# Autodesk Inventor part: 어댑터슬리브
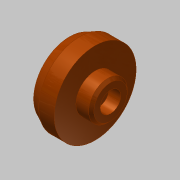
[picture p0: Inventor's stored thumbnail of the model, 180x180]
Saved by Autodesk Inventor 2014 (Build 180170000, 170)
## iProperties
Created: 2016-06
Part Number: 어댑터슬리브
Material: 강철, 탄소
Document SubType Name: Modeling
Designer: mduedu
Density: 7.87 g/cm^3
Appearance: Smooth - Light Orange
Author: mduedu
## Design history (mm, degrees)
sketch "스케치2"
  geometry: L1 (0, 0)-(0, 14); L2 (0, 14)-(-4, 16); L3 (-4, 16)-(-10, 16); L4 (-10, 16)-(-10, 7.5); L5 (-10, 7.5)-(-16, 7.5); L6 (-16, 7.5)-(-16, 0); L7 (-16, 0)-(0, 0)
  constraints: 14 end point, 4 parallel, 1 perpendicular, 1 vertical
  dimensions: "d0" = 32 diameter of L3 L7; "d2" = 28 diameter of L1.end L7; "d3" = 6 distance of L2.end L3.end; "d4" = 6 distance of L4.end L5.end; "d5" = 15 diameter of L5 L7; "d6" = 16 distance between parallel lines of L6 L1
revolve "회전1" sketch "스케치2" stored, may be unused: angle "d7" = 90 deg
sketch "스케치3"
  geometry: L1 (-16, -7.5)-(-16, 7.5) reference; L2 (-16, 7.5)-(-10, 7.5) reference; L3 (-10, 7.5)-(-10, 16) reference; L4 (-10, 16)-(-4, 16) reference; L5 (-4, 16)-(0, 14) reference; L6 (0, 14)-(0, -14) reference; L7 (0, -14)-(-4, -16) reference; L8 (-4, -16)-(-10, -16) reference; L9 (-10, -16)-(-10, -7.5) reference; L10 (-10, -7.5)-(-16, -7.5) reference; L11 (0, 10)-(-5, 10); L12 (-5, 10)-(-5, 8); L13 (-5, 8)-(-7, 6); L14 (-7, 6)-(-7, 0); L15 (-7, 0)-(0, 0); L16 (0, 10)-(0, 0)
  constraints: 12 end point, 3 parallel, 2 perpendicular, 1 point on line
  dimensions: "d8" = 20 diameter of L11 L15; "d10" = 16 diameter of L12.end L15; "d11" = 12 diameter of L13.end L15; "d12" = 9 distance between parallel lines of L14 L1; "d13" = 2 distance between parallel lines of L12 L14
revolve "회전2" sketch "스케치3" stored, may be unused: angle "d14" = 90 deg
chamfer "모따기1" distance "d15" = 1; stored, may be unused: second distance "d16" = 2, angle "d17" = 45 deg
sketch "스케치4"
  geometry: 2 further points
  constraints: 1 coincident
sketch "스케치5"
  geometry: 1 further point
hole "구멍1" sketch "스케치5" at (0, 0) diameter "d18" = 4.5; stored, may be unused: countersink angle "d22" = 90 deg, drill point angle "d24" = 0 deg; dims "d19" = 6, "d20" = 8, "d21" = 4.6, "d23" = 8
node "솔리드1"
node "절단 모서리 투영1"
